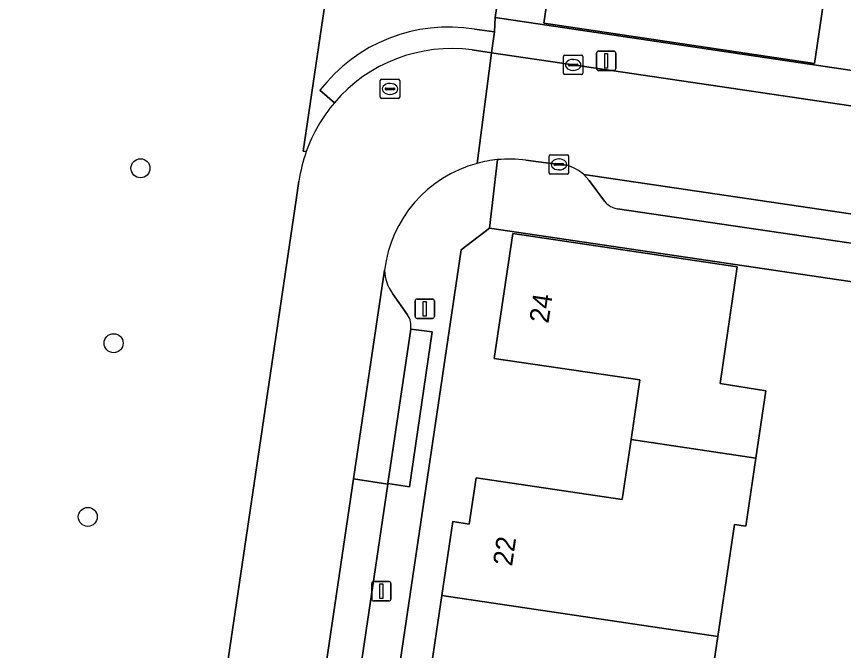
# Model space of a CAD drawing. Extents: x 164148 to 165261, y 382513 to 383432.
# Drawn here: x 164471.64 to 164514.2, y 382967.45 to 383000.07 of the extents above; entities that cross this region are included whole.
import ezdxf

# ---------------------------------------------------------------- set-up
doc = ezdxf.new("R2010")
doc.units = 0
for name, color, linetype in [('IMGEO_Boom', 7, 'Continuous'), ('IMGEO_Erf', 7, 'Continuous'), ('IMGEO_Groenvoorziening', 7, 'Continuous'), ('IMGEO_Kolk', 7, 'Continuous'), ('IMGEO_Lichtmast', 7, 'Continuous'), ('IMGEO_Pand', 7, 'Continuous'), ('IMGEO_Pand_nummerreeks', 7, 'Continuous'), ('IMGEO_Parkeervlak_open', 7, 'Continuous'), ('IMGEO_Rijbaan_lokaal_open', 7, 'Continuous'), ('IMGEO_Rioolput', 7, 'Continuous'), ('IMGEO_Voetpad_open', 7, 'Continuous')]:
    doc.layers.add(name, color=color, linetype=linetype)

msp = doc.modelspace()

# ---------------------------------------------------------------- linework, layer by layer
at = {"layer": 'IMGEO_Boom'}
for centre in [(164478.019, 382992.26), (164476.639, 382983.259), (164475.308, 382974.321)]:
    msp.add_circle(centre, 0.489, dxfattribs=at)
at = {"layer": 'IMGEO_Erf'}
for points in [[(164515.519, 383016.715), (164514.115, 383007.187), (164512.711, 382997.659), (164498.772, 382999.727), (164499.73, 383006.146), (164507.24, 383005.025), (164507.703, 383008.132), (164508.161, 383011.199), (164500.641, 383012.312), (164501.59, 383018.76), (164499.092, 383019.13), (164499.063, 383018.935), (164496.276, 383000.022), (164545.95, 382992.647)], [(164492.965, 382966.452), (164493.531, 382970.275), (164494.094, 382974.076), (164494.938, 382973.951), (164495.29, 382976.335), (164502.806, 382975.224), (164503.266, 382978.299), (164503.726, 382981.374), (164496.22, 382982.478), (164497.179, 382988.9), (164508.726, 382987.192), (164507.855, 382981.183), (164510.212, 382980.811), (164509.697, 382977.337), (164509.179, 382973.842), (164508.589, 382973.93), (164507.734, 382968.167), (164506.878, 382962.404)]]:
    msp.add_lwpolyline(points, dxfattribs=at)
msp.add_lwpolyline([(164536.67, 382930.425), (164544.133, 382980.726), (164542.913, 382982.243), (164519.298, 382985.737), (164495.986, 382989.176), (164494.523, 382988.072), (164478.67, 382881.048), (164478.137, 382876.668), (164527.73, 382869.322)], close=True, dxfattribs=at)
at = {"layer": 'IMGEO_Groenvoorziening'}
for points in [[(164486.551, 382993.124), (164486.385, 382993.149), (164490.395, 383020.195), (164490.427, 383020.412), (164473.524, 383022.914), (164465.774, 382970.421), (164463.056, 382952.005), (164462.736, 382949.84), (164455.277, 382898.839)], [(164486.03, 382990.645), (164486.178, 382991.604)], [(164472.108, 382896.577), (164486.03, 382990.645)]]:
    msp.add_lwpolyline(points, dxfattribs=at)
msp.add_arc((164494.057, 382990.476), 7.959, 160.5698, 171.8549, dxfattribs=at)
at = {"layer": 'IMGEO_Kolk'}
for p, q in [((164499.787, 382997.153), (164499.787, 382998.005)), ((164499.862, 382998.079), (164500.714, 382998.079)), ((164500.275, 382997.859), (164500.3, 382997.859)), ((164500.788, 382998.005), (164500.788, 382997.153)), ((164500.046, 382997.573), (164500.046, 382997.585)), ((164500.484, 382997.536), (164500.086, 382997.536)), ((164500.089, 382997.622), (164500.487, 382997.622)), ((164500.298, 382997.299), (164500.273, 382997.299)), ((164500.53, 382997.585), (164500.53, 382997.573)), ((164500.714, 382997.079), (164499.862, 382997.079)), ((164499.055, 382992.033), (164499.055, 382992.885)), ((164499.13, 382992.959), (164499.982, 382992.959)), ((164499.543, 382992.739), (164499.568, 382992.739)), ((164500.056, 382992.885), (164500.056, 382992.033)), ((164499.314, 382992.453), (164499.314, 382992.465)), ((164499.752, 382992.416), (164499.354, 382992.416)), ((164499.357, 382992.502), (164499.755, 382992.502)), ((164499.798, 382992.465), (164499.798, 382992.453)), ((164499.982, 382991.959), (164499.13, 382991.959)), ((164499.566, 382992.179), (164499.541, 382992.179))]:
    msp.add_line(p, q, dxfattribs=at)
for points in [[(164499.787, 382997.153), (164499.787, 382998.005)], [(164499.862, 382998.079), (164500.714, 382998.079)], [(164500.788, 382998.005), (164500.788, 382997.153)], [(164500.714, 382997.079), (164499.862, 382997.079)], [(164499.055, 382992.033), (164499.055, 382992.885)], [(164499.13, 382992.959), (164499.982, 382992.959)], [(164500.056, 382992.885), (164500.056, 382992.033)], [(164499.982, 382991.959), (164499.13, 382991.959)]]:
    msp.add_lwpolyline(points, dxfattribs=at)
for centre, radius, start, end in [((164499.864, 382998.003), 0.0765, 91.552, 178.448), ((164499.864, 382998.003), 0.0765, 91.552, 178.448), ((164500.712, 382998.003), 0.0765, 1.552, 88.448), ((164500.712, 382998.003), 0.0765, 1.552, 88.448), ((164500.086, 382997.582), 0.0403, 85.8775, 175.7526), ((164500.083, 382997.572), 0.0366, 178.938, 274.7102), ((164500.487, 382997.579), 0.043, 264.8664, 352.4533), ((164500.491, 382997.584), 0.0386, 1.7309, 96.639), ((164499.864, 382997.155), 0.0765, 181.552, 268.448), ((164499.864, 382997.155), 0.0765, 181.552, 268.448), ((164500.712, 382997.155), 0.0765, 271.552, 358.448), ((164500.712, 382997.155), 0.0765, 271.552, 358.448), ((164499.132, 382992.883), 0.0765, 91.552, 178.448), ((164499.132, 382992.883), 0.0765, 91.552, 178.448), ((164499.98, 382992.883), 0.0765, 1.552, 88.448), ((164499.98, 382992.883), 0.0765, 1.552, 88.448), ((164499.354, 382992.462), 0.0403, 85.8775, 175.7526), ((164499.351, 382992.452), 0.0366, 178.938, 274.7102), ((164499.755, 382992.459), 0.043, 264.8664, 352.4533), ((164499.759, 382992.464), 0.0386, 1.7309, 96.639), ((164499.132, 382992.035), 0.0765, 181.552, 268.448), ((164499.132, 382992.035), 0.0765, 181.552, 268.448), ((164499.98, 382992.035), 0.0765, 271.552, 358.448), ((164499.98, 382992.035), 0.0765, 271.552, 358.448)]:
    msp.add_arc(centre, radius, start, end, dxfattribs=at)
for centre, major_axis, ratio, start_param, end_param in [((164500.274, 382997.579), (-0.387, 0.002), 0.722429, 4.712389, 7.853982), ((164500.299, 382997.579), (-0.39, 0.002), 0.717154, 1.570796, 4.712389), ((164499.542, 382992.459), (-0.387, 0.002), 0.722429, 4.712389, 7.853982), ((164499.567, 382992.459), (-0.39, 0.002), 0.717154, 1.570796, 4.712389)]:
    msp.add_ellipse(centre, major_axis=major_axis, ratio=ratio, start_param=start_param, end_param=end_param, dxfattribs=at)
at = {"layer": 'IMGEO_Lichtmast'}
for p, q in [((164501.492, 382997.389), (164501.492, 382998.189)), ((164501.492, 382998.189), (164501.492, 382997.389)), ((164501.592, 382998.289), (164502.382, 382998.289)), ((164502.382, 382998.289), (164501.592, 382998.289)), ((164502.482, 382998.189), (164502.482, 382997.389)), ((164502.482, 382997.389), (164502.482, 382998.189)), ((164502.382, 382997.289), (164501.592, 382997.289)), ((164501.592, 382997.289), (164502.382, 382997.289)), ((164492.154, 382984.632), (164492.154, 382985.432)), ((164492.154, 382985.432), (164492.154, 382984.632)), ((164492.254, 382985.532), (164493.044, 382985.532)), ((164493.044, 382985.532), (164492.254, 382985.532)), ((164493.144, 382985.432), (164493.144, 382984.632)), ((164493.144, 382984.632), (164493.144, 382985.432)), ((164493.044, 382984.532), (164492.254, 382984.532)), ((164492.254, 382984.532), (164493.044, 382984.532)), ((164490.023, 382970.996), (164490.813, 382970.996)), ((164490.813, 382970.996), (164490.023, 382970.996)), ((164489.923, 382970.096), (164489.923, 382970.896)), ((164489.923, 382970.896), (164489.923, 382970.096)), ((164490.913, 382970.896), (164490.913, 382970.096)), ((164490.913, 382970.096), (164490.913, 382970.896)), ((164490.813, 382969.996), (164490.023, 382969.996)), ((164490.023, 382969.996), (164490.813, 382969.996))]:
    msp.add_line(p, q, dxfattribs=at)
for points in [[(164501.912, 382998.164), (164502.062, 382998.164), (164502.062, 382997.414), (164501.912, 382997.414), (164501.912, 382998.164)], [(164492.574, 382985.407), (164492.724, 382985.407), (164492.724, 382984.657), (164492.574, 382984.657), (164492.574, 382985.407)], [(164490.343, 382970.871), (164490.493, 382970.871), (164490.493, 382970.121), (164490.343, 382970.121), (164490.343, 382970.871)]]:
    msp.add_lwpolyline(points, dxfattribs=at)
for centre, start, end in [((164501.592, 382998.189), 90, 180), ((164501.592, 382998.189), 90, 180), ((164502.382, 382998.189), 0, 90), ((164502.382, 382998.189), 360, 90), ((164501.592, 382997.389), 180, 270), ((164501.592, 382997.389), 180, 270), ((164502.382, 382997.389), 270, 0), ((164502.382, 382997.389), 270, 0), ((164492.254, 382985.432), 90, 180), ((164492.254, 382985.432), 90, 180), ((164493.044, 382985.432), 0, 90), ((164493.044, 382985.432), 360, 90), ((164492.254, 382984.632), 180, 270), ((164492.254, 382984.632), 180, 270), ((164493.044, 382984.632), 270, 0), ((164493.044, 382984.632), 270, 0), ((164490.023, 382970.896), 90, 180), ((164490.023, 382970.896), 90, 180), ((164490.813, 382970.896), 0, 90), ((164490.813, 382970.896), 360, 90), ((164490.023, 382970.096), 180, 270), ((164490.023, 382970.096), 180, 270), ((164490.813, 382970.096), 270, 0), ((164490.813, 382970.096), 270, 0)]:
    msp.add_arc(centre, 0.1, start, end, dxfattribs=at)
at = {"layer": 'IMGEO_Pand'}
for points in [[(164514.115, 383007.187), (164507.703, 383008.132), (164507.24, 383005.025), (164499.73, 383006.146), (164498.772, 382999.727), (164512.711, 382997.659)], [(164508.726, 382987.192), (164497.179, 382988.9), (164496.22, 382982.478), (164503.726, 382981.374), (164503.266, 382978.299), (164509.697, 382977.337), (164510.212, 382980.811), (164507.855, 382981.183)], [(164508.589, 382973.93), (164509.179, 382973.842), (164509.697, 382977.337), (164503.266, 382978.299), (164502.806, 382975.224), (164495.29, 382976.335), (164494.938, 382973.951), (164494.094, 382974.076), (164493.531, 382970.275), (164507.734, 382968.167)], [(164507.734, 382968.167), (164493.531, 382970.275), (164492.965, 382966.452), (164493.813, 382966.327), (164493.462, 382963.942), (164500.979, 382962.835), (164500.524, 382959.772), (164506.962, 382958.826), (164507.474, 382962.308), (164506.878, 382962.404)]]:
    msp.add_lwpolyline(points, close=True, dxfattribs=at)
at = {"layer": 'IMGEO_Parkeervlak_open'}
for points in [[(164500.834, 382991.936), (164500.976, 382991.792), (164501.104, 382991.636), (164501.907, 382990.563)], [(164537.994, 382985.229), (164539.112, 382986.053), (164539.274, 382986.156), (164539.445, 382986.242), (164500.834, 382991.936)], [(164502.575, 382990.175), (164537.247, 382985.085)]]:
    msp.add_lwpolyline(points, dxfattribs=at)
msp.add_lwpolyline([(164490.746, 382975.998), (164488.991, 382976.277), (164487.446, 382965.833), (164489.205, 382965.585)], close=True, dxfattribs=at)
msp.add_arc((164502.703, 382991.164), 0.997, 217.0529, 262.6478, dxfattribs=at)
at = {"layer": 'IMGEO_Rijbaan_lokaal_open'}
for points in [[(164499.063, 383018.935), (164495.689, 383019.425), (164493.71, 383019.713), (164490.395, 383020.195), (164486.385, 382993.149), (164486.551, 382993.124)], [(164495.209, 382999.416), (164496.241, 382999.283), (164496.276, 383000.022), (164499.063, 383018.935)], [(164495.341, 382992.514), (164496.078, 382998.202), (164495.09, 382998.348)], [(164547.31, 382990.624), (164546.318, 382990.771), (164540.894, 382991.575), (164521.081, 382994.507), (164500.288, 382997.579), (164496.078, 382998.202), (164495.341, 382992.514)], [(164487.999, 382995.636), (164487.258, 382996.275)], [(164497.858, 382992.682), (164499.556, 382992.459), (164499.941, 382992.416)], [(164500.834, 382991.936), (164539.445, 382986.242)], [(164486.178, 382991.604), (164486.03, 382990.645), (164472.108, 382896.577)], [(164488.991, 382976.277), (164490.58, 382987.013)], [(164476.532, 382892.042), (164476.696, 382893.15), (164476.868, 382894.336), (164477.996, 382901.958), (164479.16, 382909.83), (164480.788, 382920.832), (164481.951, 382928.698), (164483.373, 382938.31), (164483.514, 382939.266), (164484.677, 382947.121), (164486.275, 382957.923), (164487.446, 382965.833), (164488.991, 382976.277)]]:
    msp.add_lwpolyline(points, dxfattribs=at)
for centre, radius, start, end in [((164493.858, 382991.202), 8.324, 80.6599, 142.4526), ((164494.034, 382990.483), 7.936, 82.354, 139.5054), ((164494.017, 382990.494), 7.915, 139.4858, 160.593), ((164494.017, 382990.494), 7.915, 139.4858, 160.593), ((164494.057, 382990.476), 7.959, 160.5698, 171.8549), ((164497.035, 382986.167), 6.569, 95.595, 104.9477), ((164497.024, 382986.203), 6.533, 82.6694, 95.5293), ((164497.026, 382986.245), 6.491, 105.0411, 173.2079), ((164499.429, 382990.394), 2.086, 47.6784, 75.8043)]:
    msp.add_arc(centre, radius, start, end, dxfattribs=at)
at = {"layer": 'IMGEO_Rioolput'}
for p, q in [((164490.362, 382995.918), (164490.362, 382996.77)), ((164490.437, 382996.844), (164491.289, 382996.844)), ((164490.85, 382996.624), (164490.875, 382996.624)), ((164491.363, 382996.77), (164491.363, 382995.918)), ((164490.621, 382996.338), (164490.621, 382996.35)), ((164491.059, 382996.301), (164490.661, 382996.301)), ((164490.664, 382996.387), (164491.062, 382996.387)), ((164490.873, 382996.064), (164490.848, 382996.064)), ((164491.105, 382996.35), (164491.105, 382996.338)), ((164491.289, 382995.844), (164490.437, 382995.844))]:
    msp.add_line(p, q, dxfattribs=at)
for points in [[(164490.362, 382995.918), (164490.362, 382996.77)], [(164490.437, 382996.844), (164491.289, 382996.844)], [(164491.363, 382996.77), (164491.363, 382995.918)], [(164491.289, 382995.844), (164490.437, 382995.844)]]:
    msp.add_lwpolyline(points, dxfattribs=at)
for centre, radius, start, end in [((164490.439, 382996.768), 0.0765, 91.552, 178.448), ((164490.439, 382996.768), 0.0765, 91.552, 178.448), ((164491.287, 382996.768), 0.0765, 1.552, 88.448), ((164491.287, 382996.768), 0.0765, 1.552, 88.448), ((164490.661, 382996.347), 0.0403, 85.8775, 175.7526), ((164490.658, 382996.337), 0.0366, 178.938, 274.7102), ((164491.062, 382996.344), 0.043, 264.8664, 352.4533), ((164491.066, 382996.349), 0.0386, 1.7309, 96.639), ((164490.439, 382995.92), 0.0765, 181.552, 268.448), ((164490.439, 382995.92), 0.0765, 181.552, 268.448), ((164491.287, 382995.92), 0.0765, 271.552, 358.448), ((164491.287, 382995.92), 0.0765, 271.552, 358.448)]:
    msp.add_arc(centre, radius, start, end, dxfattribs=at)
for centre, major_axis, ratio, start_param, end_param in [((164490.849, 382996.344), (-0.387, 0.002), 0.722429, 4.712389, 7.853982), ((164490.874, 382996.344), (-0.39, 0.002), 0.717154, 1.570796, 4.712389)]:
    msp.add_ellipse(centre, major_axis=major_axis, ratio=ratio, start_param=start_param, end_param=end_param, dxfattribs=at)
at = {"layer": 'IMGEO_Voetpad_open'}
for points in [[(164544.373, 382910.128), (164544.836, 382913.278), (164547.639, 382932.325), (164548.516, 382938.237), (164548.985, 382941.401), (164552.672, 382966.272), (164553.143, 382969.448), (164556.835, 382994.343), (164557.306, 382997.521), (164559.158, 383010.01), (164557.674, 383010.23), (164555.696, 383010.523), (164548.758, 383011.551), (164545.95, 382992.647), (164496.276, 383000.022), (164496.241, 382999.283), (164496.078, 382998.202), (164500.288, 382997.579), (164521.081, 382994.507), (164540.894, 382991.575), (164546.318, 382990.771), (164546.491, 382991.867), (164547.511, 382991.704)], [(164495.09, 382998.348), (164496.078, 382998.202), (164496.241, 382999.283), (164495.209, 382999.416)], [(164487.258, 382996.275), (164487.999, 382995.636)], [(164494.523, 382988.072), (164495.986, 382989.176), (164496.395, 382992.705)], [(164496.395, 382992.705), (164495.986, 382989.176), (164519.298, 382985.737), (164542.913, 382982.243), (164544.133, 382980.726), (164536.67, 382930.425), (164527.73, 382869.322), (164527.513, 382867.841), (164528.255, 382867.732), (164528.242, 382867.643), (164527.339, 382861.387), (164526.374, 382854.707)], [(164499.941, 382992.416), (164499.556, 382992.459), (164497.858, 382992.682)], [(164501.907, 382990.563), (164501.104, 382991.636), (164500.976, 382991.792), (164500.834, 382991.936)], [(164537.247, 382985.085), (164502.575, 382990.175)], [(164465.481, 382864.11), (164466.481, 382870.957), (164467.374, 382877.067), (164467.712, 382879.403), (164471.849, 382882.015), (164478.67, 382881.048), (164494.523, 382988.072)], [(164490.58, 382987.013), (164488.991, 382976.277), (164490.746, 382975.998), (164490.752, 382976.033), (164491.927, 382983.978)], [(164490.989, 382985.816), (164491.769, 382984.725)], [(164491.769, 382984.725), (164490.989, 382985.816)], [(164491.927, 382983.978), (164493.026, 382983.85), (164491.862, 382975.864), (164490.752, 382976.033), (164490.746, 382975.998), (164489.205, 382965.585)]]:
    msp.add_lwpolyline(points, dxfattribs=at)
msp.add_lwpolyline([(164491.927, 382983.978), (164490.752, 382976.033), (164491.862, 382975.864), (164493.026, 382983.85)], close=True, dxfattribs=at)
for centre, radius, start, end in [((164493.858, 382991.202), 8.324, 80.6599, 142.4526), ((164494.034, 382990.483), 7.936, 82.354, 139.5054), ((164497.035, 382986.167), 6.569, 95.595, 104.9477), ((164497.024, 382986.203), 6.533, 82.6694, 95.5293), ((164497.026, 382986.245), 6.491, 105.0411, 173.2079), ((164499.429, 382990.394), 2.086, 47.6784, 75.8043), ((164502.703, 382991.164), 0.997, 217.0529, 262.6478), ((164492.807, 382987.106), 2.229, 182.3797, 215.3496), ((164492.807, 382987.106), 2.229, 182.3797, 215.3496), ((164490.865, 382984.143), 1.075, 351.1475, 32.738), ((164490.865, 382984.143), 1.075, 351.1475, 32.738)]:
    msp.add_arc(centre, radius, start, end, dxfattribs=at)

# ---------------------------------------------------------------- texts
at = {"layer": 'IMGEO_Pand_nummerreeks'}
for s, rotation, p in [('24', 81.509, (164499.012, 382984.251)), ('22', 81.6006, (164497.141, 382971.757))]:
    msp.add_text(s, height=1, rotation=rotation, dxfattribs=at).set_placement(p)

doc.saveas('drawing.dxf')
